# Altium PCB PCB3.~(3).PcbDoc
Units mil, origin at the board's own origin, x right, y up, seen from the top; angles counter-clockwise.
Board outline 954.83 x 960.81 mil, 2 copper layers (Top Layer, Bottom Layer); 36 components, 33 nets, 168 pads, 30 vias.
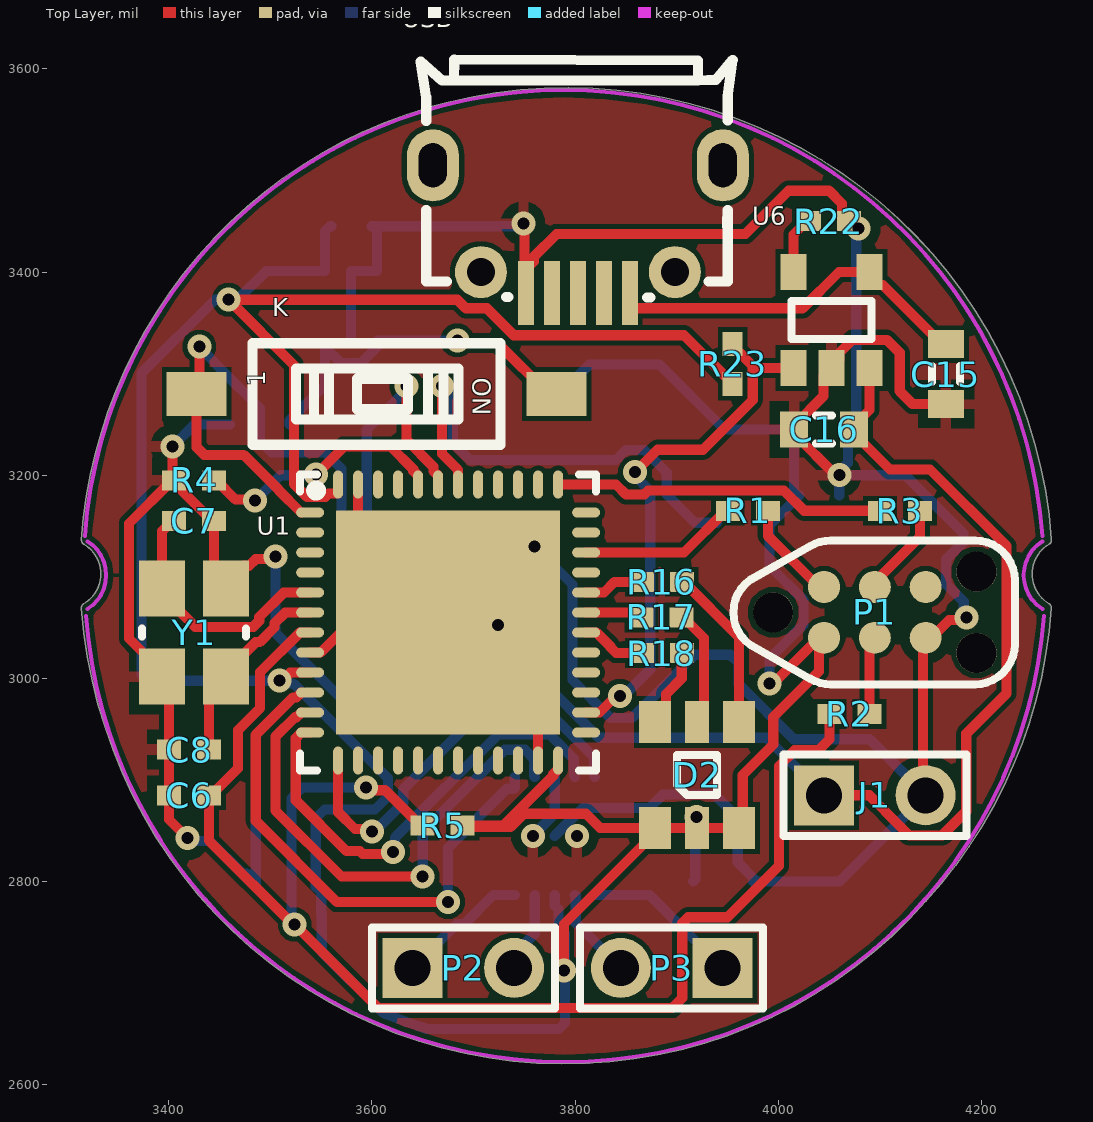
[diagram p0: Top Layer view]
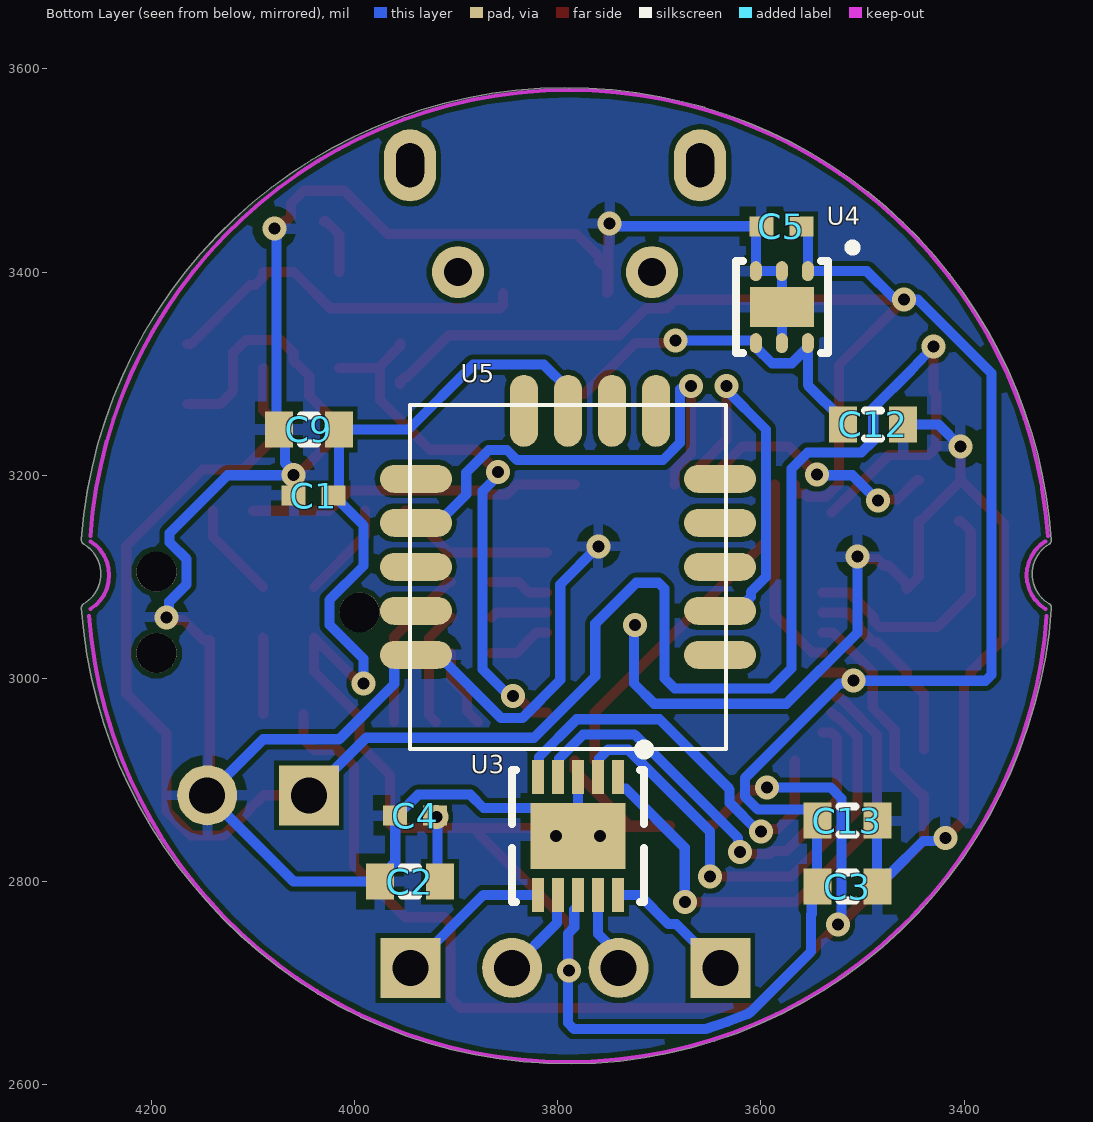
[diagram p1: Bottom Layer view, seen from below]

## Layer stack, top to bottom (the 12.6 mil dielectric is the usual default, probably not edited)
Top Solder: solder mask 0.4, Solder Resist, Dk 3.5
Top Layer: signal copper 1.4
Dielectric 1: dielectric 12.6, FR-4, Dk 4.8
Bottom Layer: signal copper 1.4
Bottom Solder: solder mask 0.4, Solder Resist, Dk 3.5

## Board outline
3314.12,3068.48 cw(c3319.06,3069.36) 3316.51,3073.68 ccw(c3299.33,3102.83) 3333.17,3102.83 ccw(c3299.33,3102.83) 3316.53,3131.98 cw(c3319.08,3136.29) 3314.08,3136.65 cw(c3791.46,3102.83) 3365.62,3321.22 cw(c3788.74,3106.63) 3722.2,3576.37 cw(c3791.46,3102.83) 4268.79,3137.19 4268.87,3136.31 cw(c4263.86,3136.31) 4266.4,3131.99 ccw(c4283.58,3102.83) 4266.38,3073.69 cw(c4263.83,3069.37) 4268.84,3069.37 4268.83,3069.02 cw(c3791.46,3102.83) 4145.43,2780.76 cw(c3790,3095) 3345.37,2929.52 cw(c3791.46,3102.83)

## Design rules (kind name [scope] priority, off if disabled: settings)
Clearance [All] p1: gap=5 ignorepadtopadclearanceinfootprint=FALSE except(0: Arc-Hole Track-Hole SMDPad-Hole THPad-Hole Via-Hole Fill-Hole Poly-Hole Region-Hole Text-Hole)
PolygonConnect [All] p1: connectstyle=Relief reliefconductorwidth=10 reliefentries=4 polygonreliefangle="90 Angle" airgapwidth=10
RoutingVias [All] p1: holewidth=28 width=50 viastyle="Through Hole" minholewidth=28 minwidth=50 maxholewidth=28 maxwidth=50
SolderMaskExpansion [All] p1: expansion=4 istentingtop=FALSE
Width [All] p1: maxlimit=10 minlimit=10 preferedwidth=10
30 further rules are at their usual default settings.

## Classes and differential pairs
net class RGBLED[1..3]: RGBLED1 RGBLED2 RGBLED3
net class MOTOR_CONTROL[1..4]: MOTOR_CONTROL1 MOTOR_CONTROL2 MOTOR_CONTROL3 MOTOR_CONTROL4

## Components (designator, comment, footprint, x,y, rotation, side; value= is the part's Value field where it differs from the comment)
C1 "10nF" 0402 4040.32,3180 r180 bottom
C2 "1uF" 0603 3945.47,2800 r180 bottom
C3 "4.7uF" 0603 3515,2795 r0 bottom
C4 "100nF" 0402 3940.32,2865 r180 bottom
C5 "100nF" 0402 3580,3445 r180 bottom
C6 "100nF" 0402 3420,2885 r0 top
C7 "22pF" 0402 3425,3155 r180 top
C8 "22pF" 0402 3420,2930 r0 top
C9 "10uF" 0603 4045,3245 r180 bottom
C12 "1uF" 0603 3489.53,3250 r0 bottom
C13 "1uF" 0603 3515,2860 r0 bottom
C15 "4.7uF" 0603 4165,3299.53 r90 top
C16 "4.7uF" 0603 4045,3245 r0 top
D2 "SMLVN6RGB1W1" "3.5x2.8 mm 6-SMD" 3920,2905 r90 top
J1 "78171-0002" HDR1*2 4095,2885 r90 top
K "2.54-1P-PGT" SW-SMD_2P-L6.2-LS9.4 3610,3280 r0 top net-tie
P1 "TC2030-IDC-NL" TC2030-IDC-NL 4095,3065 r0 top
P2 "HEADER 2X1 0.05\" UNPOLARIZED" HDR1*2 3690,2715 r90 top
P3 "HEADER 2X1 0.05\" UNPOLARIZED" HDR1*2 3895,2715 r270 top
R1 "22R" 0402 3970,3165 r0 top
R2 "22R" 0402 4070,2965 r0 top
R3 "22R" 0402 4119.69,3165 r0 top
R4 "100K" 0402 3425,3195 r0 top
R5 "100K" 0402 3669.68,2855 r0 top
R16 "22.6R" 0402 3885.31,3095 r0 top
R17 "130R" 0402 3885,3060 r0 top
R18 "24.9R" 0402 3885.31,3025 r0 top
R22 "10K" 0402 4049.68,3450 r0 top
R23 "100K" 0402 3955,3309.69 r270 top
U1 "STM32F051C8U6" QFN50P700X700X60_HS-49L 3675,3055 r0 top
U3 "A3901SEJTR-T" DFN50P300X300X75_HS-11N 3780,2845 r0 bottom
U4 "ADP122ACPZ-3.3-R7" "LFCSP-6 2.0X2.0X0.55" 3579.41,3365.43 r0 bottom
U5 "DX-BT24-T" DX-BT24-T 3790,3100 r0 bottom
U6 "MCP73831T-2ACI/OT" SOT-23-OT5_L 4052.4,3352.76 r90 top
USB "MicroXNJ" MICRO-USB-SMD_MICROXNJ 3802.71,3442.15 r180 top
Y1 "7V-16.000MAAE-T" "3.2x2.5 CRYSTAL" 3425,3045 r270 top

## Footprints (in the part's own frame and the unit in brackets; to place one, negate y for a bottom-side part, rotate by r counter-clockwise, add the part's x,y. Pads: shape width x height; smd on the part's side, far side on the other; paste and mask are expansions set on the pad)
"3.2x2.5 CRYSTAL" [mm]
  rect 1.4x1.15 smd: 1(-1.1,-0.8) 2(1.1,-0.8) 3(1.1,0.8) 4(-1.1,0.8)
  silkscreen extent -0.1,-1.3 0.1,1.3, body extent -1.6,-1.25 1.6,1.25, height 0.8
"3.5x2.8 mm 6-SMD" [mm] "3.5 x 2.8 mm 6-SMD Flat Leads"
  rect 1.05x0.8 smd: 1(-1.325,1.05) 3(-1.325,-1.05) 4(1.325,-1.05) 6(1.325,1.05)
  rect 1.05x0.6 smd: 2(-1.325,0) 5(1.325,0)
  silkscreen extent -0.5,-0.5 0.5,0.5, body extent -1.75,-1.4 1.75,1.4, height 0.6
0402 [mm] "Chip Body 1.0 x 0.5 mm (LxW typ)"
  rect 0.6x0.5 smd: 1(-0.5,0) 2(0.5,0)
  body extent -0.55,-0.3 0.55,0.3, height 0.55
0603 [mm] "Chip Body 1.6 x 0.8 mm (LxW typ)"
  rect 0.7x0.9 smd: 1(-0.75,0) 2(0.75,0)
  silkscreen extent -0.2,-0.35 0.2,0.35, body extent -0.85,-0.48 0.85,0.48, height 0.9
DFN50P300X300X75_HS-11N [mm]
  rect 0.3x0.85 smd: 1(-1,-1.475) 2(-0.5,-1.475) 3(0,-1.475) 4(0.5,-1.475) 5(1,-1.475) 6(1,1.475) 7(0.5,1.475) 8(0,1.475) 9(-0.5,1.475) 10(-1,1.475)
  rect 2.38x1.65 smd: 11(0,0)
  silkscreen extent -1.78,-2.28 1.65,1.65, body extent -1.5,-1.5 1.5,1.5, height 0.75
DX-BT24-T [mm] "DX-BT24-T"
  oval 1.8x0.7 smd: 1(-3.8,1.95) 2(-3.8,0.85) 3(-3.8,-0.25) 4(-3.8,-1.35) 5(-3.8,-2.45) 10(3.8,-2.45) 11(3.8,-1.35) 12(3.8,-0.25) 13(3.8,0.85) 14(3.8,1.95)
  oval 0.7x1.8 smd: 6(-2.2,-4.15) 7(-1.1,-4.15) 8(0,-4.15) 9(1.1,-4.15)
  silkscreen extent -3.95,-4.3 3.95,4.3
HDR1*2 [mm]
  rect 1.5x1.5 hole 0.9: 1(0,1.27)
  round 1.5 hole 0.9: 2(0,-1.27)
  silkscreen extent -1.02,-2.29 1.02,2.29
"LFCSP-6 2.0X2.0X0.55" [mm] ". 6-Lead Lead Frame Chip Scale Package [LFCSP_UD]  2.00 mm?2.00 mm Body, Ultra Thin, Dual Lead  (CP-6-3)"
  oval 0.3x0.5 smd: 1(-0.65,-0.9) 2(0,-0.9) 3(0.65,-0.9) 4(0.65,0.9) 5(0,0.9) 6(-0.65,0.9)
  rect 1.6x1 smd: 7(0,0)
  silkscreen extent -1.86,-1.59 1.15,1.15, body extent -1,-1 1,1, height 0.6
MICRO-USB-SMD_MICROXNJ [mm]
  rect 0.4x1.6 smd paste-100 mask+0.051: 1(-1.3,1.596) 2(-0.65,1.596) 3(0,1.596) 4(0.65,1.596) 5(1.3,1.596)
  round 1.3 hole 0.7: 6(2.425,1.074) 9(-2.425,1.074)
  oval 1.3x1.8 hole 0.7 slot 1.1 at 90 deg: 7(3.625,-1.596) 8(-3.625,-1.596)
  silkscreen extent -3.87,-4.24 3.93,1.71
QFN50P700X700X60_HS-49L [mm] "QFN, 48-Leads, Body 7,00x7,00mm, Pitch 0,50mm, Thermal Pad 5,60x5,60mm, IPC High Density"
  oval 0.7x0.25 smd: 1(-3.45,2.75) 2(-3.45,2.25) 3(-3.45,1.75) 4(-3.45,1.25) 5(-3.45,0.75) 6(-3.45,0.25) 7(-3.45,-0.25) 8(-3.45,-0.75) 9(-3.45,-1.25) 10(-3.45,-1.75) 11(-3.45,-2.25) 12(-3.45,-2.75) 25(3.45,-2.75) 26(3.45,-2.25) 27(3.45,-1.75) 28(3.45,-1.25) 29(3.45,-0.75) 30(3.45,-0.25) 31(3.45,0.25) 32(3.45,0.75) 33(3.45,1.25) 34(3.45,1.75) 35(3.45,2.25) 36(3.45,2.75)
  oval 0.25x0.7 smd: 13(-2.75,-3.45) 14(-2.25,-3.45) 15(-1.75,-3.45) 16(-1.25,-3.45) 17(-0.75,-3.45) 18(-0.25,-3.45) 19(0.25,-3.45) 20(0.75,-3.45) 21(1.25,-3.45) 22(1.75,-3.45) 23(2.25,-3.45) 24(2.75,-3.45) 37(2.75,3.45) 38(2.25,3.45) 39(1.75,3.45) 40(1.25,3.45) 41(0.75,3.45) 42(0.25,3.45) 43(-0.25,3.45) 44(-0.75,3.45) 45(-1.25,3.45) 46(-1.75,3.45) 47(-2.25,3.45) 48(-2.75,3.45)
  rect 5.6x5.6 smd: 49(0,0)
  silkscreen extent -3.7,-3.7 3.7,3.7, body extent -3.55,-3.55 3.55,3.55, height 0.6
SOT-23-OT5_L [mm] "SOT23, 5-Leads, Body 2.9x1.6mm, Pitch 0.95mm, Lead Span 2.7mm, IPC High Density"
  rect 0.9x0.65 smd: 1(-1.2,0.95) 2(-1.2,0) 3(-1.2,-0.95) 4(1.2,-0.95) 5(1.2,0.95)
  silkscreen extent -0.48,-1 0.48,1, body extent -0.9,-1.55 0.9,1.55, height 1.45
SW-SMD_2P-L6.2-LS9.4 [mm]
  rect 1.5x1.1 smd paste+0 mask+0.051: 1(-4.636,-0.002) 2(4.364,-0.002)
  silkscreen extent -3.24,-1.27 2.96,1.27
TC2030-IDC-NL [mm] "TagConnector TC2030-IDC-NL"
  round 0.8 smd paste-1: 1(-1.27,-0.635) 2(-1.27,0.635) 3(0,-0.635) 4(0,0.635) 5(1.27,-0.635) 6(1.27,0.635)
  round 1 hole 1 unplated mask+0: ""(-2.54,0) ""(2.54,-1.016) ""(2.54,1.016)
  Top Layer pour cut-out: -1.27,-0.085 -1.27,0.085 -1.06,0.127 -0.881,0.246 -0.762,0.425 -0.72,0.635 -0.72,0.635 -0.55,0.635 -0.496,0.396 -0.343,0.205 -0.122,0.099 0.122,0.099 0.343,0.205 0.496,0.396 0.55,0.635 0.55,0.635 0.72,0.635 0.762,0.425 0.881,0.246 1.06,0.127 1.27,0.085 1.27,0.085 1.27,-0.085 1.06,-0.127 0.881,-0.246 0.762,-0.425 0.72,-0.635 0.72,-0.635 0.55,-0.635 0.496,-0.396 0.343,-0.205 0.122,-0.099 -0.122,-0.099 -0.343,-0.205 -0.496,-0.396 -0.55,-0.635 -0.55,-0.635 -0.72,-0.635 -0.762,-0.425 -0.881,-0.246 -1.06,-0.127 -1.27,-0.085
  silkscreen extent -3.54,-1.8 3.5,1.8, body extent -1.67,-1.03 1.67,1.03, height 0

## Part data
C1: "10nF 0402 X7R 25V ±5%", Supplier Part Number 1=1692285
C2 C12 C13: "1uF 0603 X5R 10V ±10%", Supplier Part Number 1=1759399
C3 C15 C16: "4.7uF 0603 X5R 10V ±10%", Supplier Part Number 1=2362098
C4 C5 C6: "100nF 0402 X7R 16V ±10%", Supplier Part Number 1=1288252
C7 C8: "22pF 0402 NP0/CG0 50V ±5%", Supplier Part Number 1=1414580
C9: "10uF 0603 X5R 6.3V ±20%", Supplier Part Number 1=2456110
D2: "ROHM SMLVN6RGB1W1 LED Tri-Color Blue/Green/Red Chip LED 6-Pin 1411 T/RLED Tri-Color Blue/Green/Red Chip LED 6-Pin 1411", Supplier Part Number 1=755-SMLVN6RGB1W1
J1: "Molex Pico-EZmate™ Wire-to-Board Header, 2 contacts", Supplier Part Number 1=2313710
P1: "TagConnect TC2030-IDC-NL SWD Programming Connector"
R1 R2 R3: "22R 0402 1/16W ±1%", Supplier Part Number 1=2072797
R4 R5 R23: "100K 0402 1/16W ±1%", Supplier Part Number 1=2072519
R16: "22.6R 0402 1/16W ±0.05R", Supplier Part Number 1=2302454
R17: "130R 0402 1/16W ±0.05R", Supplier Part Number 1=2059115
R18: "24.9R 0402 1/16W ±0.05R", Supplier Part Number 1=2059102
R22: "10K 0402 1/16W ±1%", Supplier Part Number 1=2072517
U1: "STMICROELECTRONICS  STM32F051C8U6  MCU 32BIT CORTEX-M0 48MHZ UFQFPN-48", Supplier Part Number 1=2393638
U3: "ALLEGRO MICROSYSTEMS - A3901SEJTR-T - IC, MOTOR DRIVER", Supplier Part Number 1=1651947
U4: "Analog Devices ADP122ACPZ-3.3-R7 - 5.5 V Input, 300 mA, Low Quiescent  Current, CMOS Linear Regulator", Supplier Part Number 1=2457164
U6: "Miniature Single-Cell, Fully Integrated Li-Ion, Li-Polymer Charge Management Controller, 4.2V, 5-Pin SOT-23, Industrial Temperature, Tape and Reel", Supplier Part Number 1=1332158
USB: Core Colour=黑色, Current Rating - Power (Max)=1.8A, JLCPCB Part Class="Extended Part", LCSC Part Name="Micro-B 母 卧贴", Manufacturer="SHOU HAN(首韩)", Operating Temperature Range=-20℃~+85℃, Rated Voltage (Max)=30V
Y1: "TXC - 7V-16.000MAAE-T, 16MHZ, 30PPM, 12PF - CRYSTAL", Supplier Part Number 1=887-1462-1-ND

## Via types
v1: diameter 23.62, hole 11.81, Top Layer to Bottom Layer, 30 vias

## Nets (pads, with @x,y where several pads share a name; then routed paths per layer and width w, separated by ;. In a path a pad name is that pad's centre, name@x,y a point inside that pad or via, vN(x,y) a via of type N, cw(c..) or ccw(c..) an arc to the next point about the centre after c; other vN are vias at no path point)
+3.3V: C1.2 C2.2 C3.2 C4.2 C5.2 C9.2 C13.2 D2.1 D2.2 D2.3 P1.1 R5.2 R23.2 U1.9 U1.24 U1.48 U3.8 U4.1 U5.8 | length 3807.9
  Top Layer w10: v1@3510.31,2996.44 3519.58,3005.71 3539.09,3005.71 U1.9 ; U1.48 3566.73,3182.13 3566.65,3182.05 3557.33,3182.05 3554.05,3178.77 3535.98,3178.77 3523.21,3191.55 3523.21,3308.53 v1(3459,3372.74) 3684.04,3372.74 3692.5,3364.28 3713.04,3364.28 3739.51,3337.8 3907.2,3337.8 3948.19,3296.81 3950.16,3296.81 3955,3291.97 R23.2 ; U1.24 3783.27,2910.47 3778.5,2905.71 3778.5,2904.13 3729.37,2855 R5.2 3690.34,2854.03 3736.54,2854.03 3749.31,2866.81 3810.69,2866.81 3824.66,2852.83 D2.1 ; v1(3789,2712.74) 3789,2758.25 3878.66,2847.91 D2.1 ; v1@3995,2995 4040,3040 4040,3007.09 3995,2962.09 3995,2935 3965,2905 3965,2856.5 D2.3 D2.2 D2.1
  Bottom Layer w10: v1(3459,3372.74) 3445.51,3372.74 3373.12,3300.35 3373.12,3003.6 3378.98,2997.74 v1(3509,2997.74) 3511.61,2995.13 3522.45,2995.13 3615.81,2901.77 3615.81,2883.7 3603.04,2870.93 3553.31,2870.93 3544.53,2862.15 C13.2 ; v1@3470,3375 3495.87,3400.87 U4.1 3553.82,3440.16 3558.66,3445 C5.2 ; C3.2 3544.76,2795.24 C13.2@3544.76,2859.76 ; C3.2@3545,2795 3550.08,2789.92 3550.08,2768.14 3550.69,2767.53 3550.69,2731.12 3609.71,2672.09 3609.76,2672.05 ccw(c3616.78,2679.16) 3612.89,2669.95 ccw(c3790,3095) 3654.23,2655 ; 3654.22,2655 3784.14,2655 3790,2660.86 3790,2748.79 3783.78,2755.01 3783.78,2772.32 3780,2776.1 U3.8 ; U5.8 3790,3285.04 3813.78,3308.82 3883.17,3308.82 3946.98,3245 C9.2 C1.2@4015.47,3184.84 ; C2.2 3918.29,2802.34 3918.29,2862.66 v1(3919.46,2863.83) C4.2 ; v1(3991.26,2994.95) 3991.26,3019.28 4024.69,3052.7 4024.69,3077.3 3991.26,3110.72 3991.26,3150.64 C1.2
+5: C15.2 U6.4 USB.1 | length 371.5
  Top Layer w10: USB.1 3853.89,3367.16 3856.76,3364.29 4023.94,3364.29 4059.65,3400 U6.4 4089.8,3395.08 4097.6,3387.28 4102.83,3387.28 4161.06,3329.06 C15.2
BT_RX: U1.43 U5.2 | length 373.6
  Top Layer w10: v1(3634,3287.74) 3634,3234.78 3660.47,3208.31 3660.47,3204.21 3665.16,3199.53 U1.43
  Bottom Layer w10: v1@3635,3285 3594.96,3244.96 3594.96,3099.99 3609.96,3084.99 3609.96,3080.07 3623.49,3066.54 U5.2
BT_TX: U1.42 U5.11 | length 470
  Top Layer w10: v1(3669,3287.74) 3669,3221 3684.76,3205.24 3684.76,3190.91 U1.42
  Bottom Layer w10: v1@3679.61,3285 3679.61,3231.88 3696.49,3215 3840.2,3215 3849.95,3224.74 3868.01,3224.74 3890.12,3202.64 3890.12,3180.99 3917.95,3153.15 U5.11
CHARGING: R23.1 U1.26 U6.1 | length 531
  Top Layer w10: U1.26 3810.91,2966.5 3824.07,2966.5 3840.32,2982.74 v1(3844,2982.74) ; v1(3858.98,3202.93) 3881.05,3225 3925.8,3225 3974.84,3274.05 3974.84,3307.56 ; R23.1 3955,3327.4 3974.84,3307.56 ; U6.1 3976.89,3305.51 3974.84,3307.56
  Bottom Layer w10: v1@3845,2980 3874,3009 3874,3184.22 3858.98,3199.24 v1(3858.98,3202.93)
GND: C1.1 C2.1 C3.1 C4.1 C5.1 C6.1 C7.1 C8.1 C9.1 C12.1 C13.1 C15.1 C16.1 J1.2 P1.5 R4.1 R22.2 U1.8 U1.23 U1.47 U1.49 U3.3 U3.11 U4.2 U4.3 U4.5 U4.7 U5.14 U6.2 USB.5 Y1.2 Y1.4 | length 4657.3
  Top Layer w10: v1(3403.75,3228.26) R4.1@3403.75,3195 ; v1(3418.49,2842.87) 3400.32,2861.05 C6.1 C8.1 3400.32,2994.88 Y1.2 3393.5,3006.61 3360.87,3039.25 3360.87,3152.52 3403.35,3195 R4.1@3403.75,3195 ; v1(3505,3120) 3502.39,3117.39 3485.58,3117.39 3479.06,3110.87 3474.13,3110.87 3456.5,3093.23 Y1.4 3444.68,3100.12 C7.1 3442.72,3155 3403.75,3193.97 R4.1@3403.75,3195 ; U1.8 3539.25,3025.55 3549.53,3025.55 3586.42,3062.44 U1.49@3586.42,3143.58 ; U1.47 U1.49@3586.42,3143.58 ; v1(3749,3447.74) 3750.27,3446.47 3750.27,3380.56 USB.5 3751.53,3402.92 3759.25,3410.64 3759.25,3414.94 3781.78,3437.47 3967.47,3437.47 4010,3480 4050,3480 4062.56,3467.44 4062.56,3454.84 4067.4,3450 R22.2 ; U1.23 3763.58,2966.42 U1.49 U1.49@3586.42,3143.58 ; v1(4060,3200) 4056.54,3200 4015.47,3241.06 C16.1 4015.47,3248.94 4044.61,3278.07 4044.61,3297.72 U6.2 4060.2,3313.31 4060.2,3320.56 4072.87,3333.23 4106.74,3333.23 4119.51,3320.46 4119.51,3282.77 4132.28,3270 C15.1 ; J1.2 4142.5,2887.5 4142.5,3037.5 4148.32,3037.5 4168.3,3057.49 4182.37,3057.49 v1(4184.97,3060.09)
  Bottom Layer w10: v1(3403.75,3228.26) 3425.48,3250 C12.1 ; v1@3420,2840 3440.47,2840 3472.76,2807.72 3476.69,2807.72 3485.47,2798.94 C3.1 3485.71,2795.24 3485.71,2859.76 C13.1@3485.94,2860 ; v1(3505,3120) 3505,3045 3575,2975 3705,2975 3725,2995 v1@3725,3050 ; U4.5 U4.7 U4.2 U4.3 C5.1@3605,3440.16 ; C5.1 v1@3750,3445 ; v1(3758.35,2845) 3780,2866.65 U3.3 ; v1(3760,3130) 3797.48,3092.52 3797.48,2998.41 3834.97,2960.93 3855.65,2960.93 3917.95,3023.23 U5.14 3952.81,3023.23 3960.92,3015.12 3960.92,2994.45 4015.22,2940.15 4089.85,2940.15 J1.2 4060,2800 C2.1 3975,2803.94 3960,2818.94 C4.1 3958.03,2865 3937.39,2885.64 3886.2,2885.64 3873.04,2872.48 3807.48,2872.48 U3.11 ; C1.1 v1(4060,3200) ; v1(4079,3442.74) 4076.76,3440.5 4076.76,3247.24 C9.1 4074.53,3238.21 4068.6,3232.28 4068.6,3212.28 4060,3203.69 v1(4060,3200) ; v1(4184.97,3060.09) 4182.49,3062.57 4182.49,3075.53 4165.31,3092.7 4165.31,3117.3 4182.11,3134.09 4182.11,3142.89 4125,3200 v1(4060,3200)
  other v1: 3801.65,2845 3724,3052.74
IMU_INT: U1.25
MCU_X1_16MHZ: C7.2 U1.5 Y1.1 | length 258
  Top Layer w10: Y1.1 Y1.1@3393.5,3093.23 ; C7.2 3403.35,3155 3393.5,3145.16 Y1.1@3393.5,3093.23 ; U1.5 3539.09,3084.45 3513.12,3084.45 3489.13,3060.47 3489.13,3056.61 3483.28,3050.75 3426.14,3050.75 3393.5,3083.39 Y1.1@3393.5,3093.23
MCU_X2_16MHZ: C8.2 U1.6 Y1.3 | length 192.6
  Top Layer w10: C8.2 3439.69,2984.88 Y1.3 3456.5,3006.61 3485.63,3035.75 3489.49,3035.75 3504.13,3050.39 3504.13,3054.25 3514.65,3064.76 3539.09,3064.76 U1.6
MOTOR_CONTROL1: U1.10 U3.1 | length 523.2
  Top Layer w10: U1.10@3530.39,2986.02 3525.71,2981.34 3522.61,2981.34 3485.71,2944.44 3485.71,2859.76 3565.47,2780 v1(3675,2780)
  Bottom Layer w10: v1(3675,2780) 3675,2833.47 3732.87,2891.34 3739.72,2891.34 3740.63,2892.24 U3.1
MOTOR_CONTROL2: U1.11 U3.2 | length 488.7
  Top Layer w10: U1.11@3530.39,2966.34 3525.79,2961.73 3524.21,2961.73 3505,2942.52 3505,2870 3570,2805 v1(3650,2805)
  Bottom Layer w10: v1(3650,2805) 3650,2849.22 3730.58,2929.8 3750.68,2929.8 3759.41,2921.07 3759.41,2903.98 U3.2
MOTOR_CONTROL3: U1.12 U3.4 | length 457.1
  Top Layer w10: U1.12 3530.47,2946.73 3525,2941.26 3525,2880 3575,2830 3588.27,2830 3590.97,2827.31 3618.66,2827.31 v1(3620.69,2829.34)
  Bottom Layer w10: v1(3620.69,2829.34) 3622.61,2831.26 3622.61,2843.04 3724.37,2944.8 3775.05,2944.8 3798.78,2921.07 3798.78,2903.98 U3.4
MOTOR_CONTROL4: U1.13 U3.5 | length 399.5
  Top Layer w10: U1.13 3566.73,2868.29 3583.3,2851.72 3597.39,2851.72 v1(3600,2849.12)
  Bottom Layer w10: v1(3600,2849.12) 3602.44,2849.12 3630.81,2877.49 3630.81,2890.81 3699.8,2959.8 3781.26,2959.8 3818.46,2922.6 3818.46,2903.98 U3.5
NetC12_2: C12.2 K.2 U4.4 U4.6 | length 361.5
  Top Layer w10: v1@3685,3330 3723.86,3330 3773.94,3279.93 K.2
  Bottom Layer w10: C12.2 3519.06,3253.94 3553.82,3288.7 U4.6@3553.82,3326.06 ; U4.6 U4.6@3553.82,3326.06 ; v1(3684,3332.74) 3605.84,3332.74 3605,3331.9 U4.4 3605,3326.06 3589.09,3310.16 3569.72,3310.16 U4.6@3553.82,3326.06
NetD2_4: D2.4 R16.2 | length 162.3
  Top Layer w10: R16.2 3906.97,3095 3961.34,3040.63 D2.4
NetD2_5: D2.5 R17.2 | length 116
  Top Layer w10: R17.2 3906.65,3060 3926.81,3039.84 3926.81,2963.98 D2.5
NetD2_6: D2.6 R18.2 | length 78.7
  Top Layer w10: D2.6 3889.41,2967.91 3889.41,2984.57 3905,3000.16 R18.2
NetP1_2: P1.2 R1.2 | length 95.8
  Top Layer w10: R1.2 3989.69,3140.31 P1.2@4040,3090
NetP1_3: P1.3 R2.2 | length 75.1
  Top Layer w10: R2.2 4089.84,2965.16 4089.84,3039.84 P1.3@4090,3040
NetP1_4: P1.4 R3.2 | length 95.4
  Top Layer w10: P1.4@4090,3090 4139.37,3139.37 R3.2
NetP2_1: P2.1 U3.10 | length 130.4
  Bottom Layer w10: P2.1 3683.19,2758.19 3690.98,2758.19 3719.72,2786.93 U3.10
NetP2_2: P2.2 U3.9 | length 80.3
  Bottom Layer w10: P2.2 3740,2728.27 3760.31,2748.59 U3.9
NetP3_1: P3.1 U3.6 | length 155.4
  Bottom Layer w10: U3.6 3873.07,2786.93 P3.1
NetP3_2: P3.2 U3.7 | length 90.7
  Bottom Layer w10: U3.7 3800.59,2786.02 3800.59,2759.41 P3.2
NetR4_2: R4.2 U1.44 | length 252.6
  Top Layer w10: R4.2 3446.65,3195 3465.64,3176.02 3483.98,3176.02 v1(3485,3175) ; v1(3545.02,3200.59) 3572.64,3228.21 3618.37,3228.21 3640.71,3205.87 3640.71,3204.29 3645.47,3199.53 U1.44
  Bottom Layer w10: v1(3485,3175) 3510,3200 3544.43,3200 v1(3545.02,3200.59)
NetR22_1: R22.1 U6.5 | length 57.4
  Top Layer w10: U6.5 4015,3436.97 4028.03,3450 R22.1
NRST: C6.2 R2.1 R5.1 U1.7 | length 1447.3
  Top Layer w10: v1(3524,2757.74) 3601.74,2680 3601.8,2680 3606.33,2675.47 3895.47,2675.47 3905.47,2685.47 3905.47,2759.14 3911.33,2765 3950,2765 4000.61,2815.61 4000.61,2913.81 4016.22,2929.41 4039.57,2929.41 4050.32,2940.16 R2.1 ; v1@3525,2755 3439.69,2840.31 C6.2 3441.65,2885 3468.25,2911.59 3468.25,2949.11 3490,2970.86 3490,3006.26 3528.82,3045.08 3539.09,3045.08 U1.7 ; v1@3595,2890 3613.03,2890 3648.03,2855 R5.1 R5.1@3651.97,2855
  Bottom Layer w10: v1@3525,2755 3520.75,2759.25 3520.75,2881.86 3531.63,2892.74 v1(3594,2892.74)
RGBLED1: R17.1 U1.31 | length 56.5
  Top Layer w10: U1.31 3810.91,3064.76 3860.55,3064.76 R17.1
RGBLED2: R16.1 U1.32 | length 59.1
  Top Layer w10: U1.32 3810.91,3084.61 3828.43,3084.61 3838.82,3095 R16.1
RGBLED3: R18.1 U1.30 | length 63.6
  Top Layer w10: U1.30 3810.91,3045.08 3821.18,3045.08 3834.61,3031.65 3834.61,3030.86 3840.46,3025 R18.1
SWCLK: R3.1 U1.37 | length 330.5
  Top Layer w10: U1.37 3840.24,3190.83 3849.95,3181.12 3868.01,3181.12 3871.74,3184.84 4005.64,3184.84 4025.48,3165 R3.1
SWDIO: R1.1 U1.34 | length 156.5
  Top Layer w10: U1.34 3907.24,3123.9 3948.35,3165 R1.1
VBAT: C16.2 J1.1 K.1 U1.1 U6.3 | length 2041.1
  Top Layer w10: v1(3430.18,3326.56) 3430.18,3282.62 K.1 3427.48,3227.52 3435,3220 3473.74,3220 3508.21,3185.53 3508.21,3185.34 3529.77,3163.77 3529.97,3163.77 U1.1@3530.39,3163.35 ; J1.1 4089.53,2885 4105.47,2869.06 4105.47,2868.63 4128.63,2845.47 4161.37,2845.47 4185,2869.1 4185,2945.63 4224.69,2985.31 4224.69,3130.31 4149.37,3205.63 4109.96,3205.63 4074.53,3241.06 C16.2 4074.53,3248.94 4089.8,3264.21 U6.3
  Bottom Layer w10: v1(3430.18,3326.56) 3452.17,3303.47 3489.53,3266.11 3489.53,3233.89 3501.13,3222.28 3542.8,3222.28 3542.91,3222.4 3554.05,3222.4 3570,3206.45 3570,3010 3590,2990 3685,2990 3695,3000 3695,3088.28 3700.86,3094.14 3722.73,3094.14 3763.09,3053.79 3763.09,3001.91 3823.38,2941.62 3988.38,2941.62 J1.1
pads on no net: P1. P1.6 U1.2 U1.3 U1.4 U1.14 U1.15 U1.16 U1.17 U1.18 U1.19 U1.20 U1.21 U1.22 U1.27 U1.28 U1.29 U1.33 U1.35 U1.36 U1.38 U1.39 U1.40 U1.41 U1.45 U1.46 U5.1 U5.3 U5.4 U5.5 U5.6 U5.7 U5.9 U5.10 U5.12 U5.13 USB.2 USB.3 USB.4 USB.6 USB.7 USB.8 USB.9

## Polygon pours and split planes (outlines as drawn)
GND on Top Layer "GND_L01_P000" (solid, pour order 0): 3314.12,3068.48 cw(c3319.06,3069.36) 3316.51,3073.68 ccw(c3299.33,3102.83) 3333.17,3102.83 ccw(c3299.33,3102.83) 3316.53,3131.98 cw(c3319.08,3136.29) 3314.08,3136.65 cw(c3791.46,3102.83) 3365.62,3321.22 cw(c3788.74,3106.63) 3722.2,3576.37 cw(c3791.46,3102.83) 4268.79,3137.19 4268.87,3136.31 cw(c4263.86,3136.31) 4266.4,3131.99 ccw(c4283.58,3102.83) 4266.38,3073.69 cw(c4263.83,3069.37) 4268.84,3069.37 4268.83,3069.02 cw(c3791.46,3102.83) 4145.43,2780.76 cw(c3790,3095) 3345.37,2929.52 cw(c3791.46,3102.83)
GND on Bottom Layer "GND_L02_P001" (solid, pour order 1): 3314.12,3068.48 cw(c3319.06,3069.36) 3316.51,3073.68 ccw(c3299.33,3102.83) 3333.17,3102.83 ccw(c3299.33,3102.83) 3316.53,3131.98 cw(c3319.08,3136.29) 3314.08,3136.65 cw(c3791.46,3102.83) 3365.62,3321.22 cw(c3788.74,3106.63) 3722.2,3576.37 cw(c3791.46,3102.83) 4268.79,3137.19 4268.87,3136.31 cw(c4263.86,3136.31) 4266.4,3131.99 ccw(c4283.58,3102.83) 4266.38,3073.69 cw(c4263.83,3069.37) 4268.84,3069.37 4268.83,3069.02 cw(c3791.46,3102.83) 4145.43,2780.76 cw(c3790,3095) 3345.37,2929.52 cw(c3791.46,3102.83)

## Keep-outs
Keep-Out Layer:
  lines w3.94: 3317.48,3140 cw(c3788.74,3106.63) 4260,3140 ; 3318.74,3061.63 ccw(c3790,3095) 4261.26,3061.63 ; 3320,3068.23 ccw(c3299.13,3101.62) 3320,3135 ; 4260,3068.23 cw(c4280.87,3101.62) 4260,3135

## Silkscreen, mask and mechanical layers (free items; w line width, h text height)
Mechanical 2:
  lines w10: 3319.06,3069.36 ccw(c3299.33,3102.83) 3319.08,3136.29 cw(c3791.46,3102.83) 4263.82,3136.36 ; 3319.09,3069.31 ccw(c3791.46,3102.83) 4263.83,3069.37 cw(c4283.58,3102.83) 4263.86,3136.31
